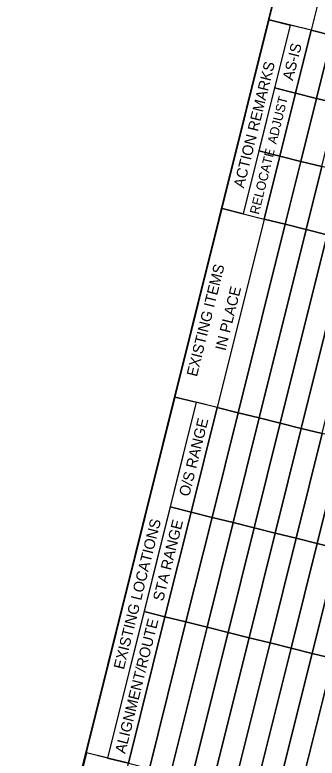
# Model space of a CAD drawing. Extents: x 2304552 to 2306093, y 413849 to 415858.
# Drawn here: x 2305141 to 2305352, y 414268 to 414787 of the extents above; entities that cross this region are included whole.
import ezdxf

# ---------------------------------------------------------------- set-up
doc = ezdxf.new("R2010")
doc.units = 0
for name, color, linetype in [('RD_SHT_Bndy', 7, 'Continuous'), ('RD_SHT_MjGrid', 7, 'Continuous'), ('RD_SHT_TX', 7, 'Continuous')]:
    doc.layers.add(name, color=color, linetype=linetype)

msp = doc.modelspace()

# ---------------------------------------------------------------- linework, layer by layer
at = {"layer": 'RD_SHT_Bndy'}
msp.add_line((2305141.49, 414072.62), (2305546.41, 415697.93), dxfattribs=at)
at = {"layer": 'RD_SHT_MjGrid'}
for points in [[(2305318.98, 414783.33), (2305348.06, 414900.03), (2305377.3, 414892.75), (2305348.22, 414776.05)], [(2305377.3, 414892.75), (2305348.22, 414776.05), (2305362.89, 414772.39), (2305391.96, 414889.1)], [(2305286.16, 414651.59), (2305318.98, 414783.33), (2305333.6, 414779.69), (2305300.78, 414647.94)], [(2305337.28, 414732.13), (2305348.22, 414776.05), (2305333.6, 414779.69), (2305322.66, 414735.77)], [(2305348.22, 414776.05), (2305337.28, 414732.13), (2305351.95, 414728.48), (2305362.89, 414772.39)], [(2305362.89, 414772.39), (2305351.95, 414728.48), (2305366.61, 414724.82), (2305377.56, 414768.74)], [(2305326.34, 414688.22), (2305337.28, 414732.13), (2305322.66, 414735.77), (2305311.72, 414691.86)], [(2305337.28, 414732.13), (2305326.34, 414688.22), (2305341.01, 414684.56), (2305351.95, 414728.48)], [(2305351.95, 414728.48), (2305341.01, 414684.56), (2305355.67, 414680.91), (2305366.61, 414724.82)], [(2305315.4, 414644.3), (2305326.34, 414688.22), (2305311.72, 414691.86), (2305300.78, 414647.94)], [(2305326.34, 414688.22), (2305315.4, 414644.3), (2305330.07, 414640.65), (2305341.01, 414684.56)], [(2305341.01, 414684.56), (2305330.07, 414640.65), (2305344.73, 414636.99), (2305355.67, 414680.91)], [(2305355.67, 414680.91), (2305344.73, 414636.99), (2305359.4, 414633.34), (2305370.34, 414677.25)], [(2305253.41, 414520.11), (2305286.16, 414651.59), (2305315.4, 414644.3), (2305282.64, 414512.83)], [(2305315.4, 414644.3), (2305282.64, 414512.83), (2305297.31, 414509.17), (2305330.07, 414640.65)], [(2305330.07, 414640.65), (2305297.31, 414509.17), (2305311.98, 414505.52), (2305344.73, 414636.99)], [(2305344.73, 414636.99), (2305311.98, 414505.52), (2305326.65, 414501.87), (2305359.4, 414633.34)], [(2305359.4, 414633.34), (2305326.65, 414501.87), (2305341.31, 414498.21), (2305374.07, 414629.69)], [(2305374.07, 414629.69), (2305341.31, 414498.21), (2305355.98, 414494.56), (2305388.73, 414626.03)], [(2305191.55, 414271.81), (2305253.41, 414520.11), (2305268.03, 414516.47), (2305206.17, 414268.17)], [(2305264.45, 414439.8), (2305282.64, 414512.83), (2305268.03, 414516.47), (2305249.83, 414443.44)], [(2305282.64, 414512.83), (2305264.45, 414439.8), (2305279.12, 414436.14), (2305297.31, 414509.17)], [(2305297.31, 414509.17), (2305279.12, 414436.14), (2305293.78, 414432.49), (2305311.98, 414505.52)], [(2305311.98, 414505.52), (2305293.78, 414432.49), (2305308.45, 414428.84), (2305326.65, 414501.87)], [(2305326.65, 414501.87), (2305308.45, 414428.84), (2305323.12, 414425.18), (2305341.31, 414498.21)], [(2305341.31, 414498.21), (2305323.12, 414425.18), (2305337.79, 414421.53), (2305355.98, 414494.56)], [(2305355.98, 414494.56), (2305337.79, 414421.53), (2305352.45, 414417.87), (2305370.65, 414490.9)], [(2305370.65, 414490.9), (2305352.45, 414417.87), (2305367.12, 414414.22), (2305385.31, 414487.25)], [(2305246.26, 414366.77), (2305264.45, 414439.8), (2305249.83, 414443.44), (2305231.64, 414370.41)], [(2305264.45, 414439.8), (2305246.26, 414366.77), (2305260.92, 414363.11), (2305279.12, 414436.14)], [(2305279.12, 414436.14), (2305260.92, 414363.11), (2305275.59, 414359.46), (2305293.78, 414432.49)], [(2305293.78, 414432.49), (2305275.59, 414359.46), (2305290.26, 414355.8), (2305308.45, 414428.84)], [(2305308.45, 414428.84), (2305290.26, 414355.8), (2305304.92, 414352.15), (2305323.12, 414425.18)], [(2305323.12, 414425.18), (2305304.92, 414352.15), (2305319.59, 414348.5), (2305337.79, 414421.53)], [(2305337.79, 414421.53), (2305319.59, 414348.5), (2305334.26, 414344.84), (2305352.45, 414417.87)], [(2305352.45, 414417.87), (2305334.26, 414344.84), (2305348.92, 414341.19), (2305367.12, 414414.22)], [(2305367.12, 414414.22), (2305348.92, 414341.19), (2305363.59, 414337.53), (2305381.79, 414410.56)], [(2305220.78, 414264.53), (2305246.26, 414366.77), (2305231.64, 414370.41), (2305206.17, 414268.17)], [(2305246.26, 414366.77), (2305220.78, 414264.53), (2305235.45, 414260.88), (2305260.92, 414363.11)], [(2305260.92, 414363.11), (2305235.45, 414260.88), (2305250.12, 414257.22), (2305275.59, 414359.46)], [(2305275.59, 414359.46), (2305250.12, 414257.22), (2305264.79, 414253.57), (2305290.26, 414355.8)], [(2305290.26, 414355.8), (2305264.79, 414253.57), (2305279.45, 414249.91), (2305304.92, 414352.15)], [(2305304.92, 414352.15), (2305279.45, 414249.91), (2305294.12, 414246.26), (2305319.59, 414348.5)], [(2305319.59, 414348.5), (2305294.12, 414246.26), (2305308.79, 414242.6), (2305334.26, 414344.84)], [(2305334.26, 414344.84), (2305308.79, 414242.6), (2305323.45, 414238.95), (2305348.92, 414341.19)], [(2305348.92, 414341.19), (2305323.45, 414238.95), (2305338.12, 414235.3), (2305363.59, 414337.53)], [(2305363.59, 414337.53), (2305338.12, 414235.3), (2305352.79, 414231.64), (2305378.26, 414333.88)], [(2305191.66, 414147.62), (2305220.78, 414264.53), (2305191.55, 414271.81), (2305162.42, 414154.9)]]:
    msp.add_lwpolyline(points, close=True, dxfattribs=at)

# ---------------------------------------------------------------- texts
at = {"layer": 'RD_SHT_TX'}
for s, height, p in [('AS-IS', 7.5, (2305335.47, 414740.5)), ('ACTION REMARKS', 7.5, (2305301.26, 414665.51)), ('ADJUST', 6.5, (2305323.91, 414696.19)), ('RELOCATE', 6.5, (2305311.68, 414647.1)), ('EXISTING ITEMS', 7.5, (2305268.5, 414533.89)), ('IN PLACE', 7.5, (2305288.46, 414551.95)), ('O/S RANGE', 7.5, (2305263.15, 414450.24)), ('EXISTING LOCATIONS', 7.5, (2305217.56, 414329.57)), ('STA RANGE', 7.5, (2305244.96, 414377.2)), ('ALIGNMENT/ROUTE', 7.5, (2305218.45, 414270.8))]:
    msp.add_text(s, height=height, rotation=76.0103, dxfattribs=at).set_placement(p)

doc.saveas('drawing.dxf')
